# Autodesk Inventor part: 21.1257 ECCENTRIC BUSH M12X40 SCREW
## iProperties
Created: 2009-01
Part Number: 21.1257 ECCENTRIC BUSH M12X40 SCREW
Document SubType Name: Modeling
Designer: Administrator
Density: 7.86 g/cm^3
Material: Steel, Mild
Mass: 42.0153 g
Surface Area: 30.9195 cm^2
Volume: 5.34545 cm^3
Author: Administrator
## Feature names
1. Base1
